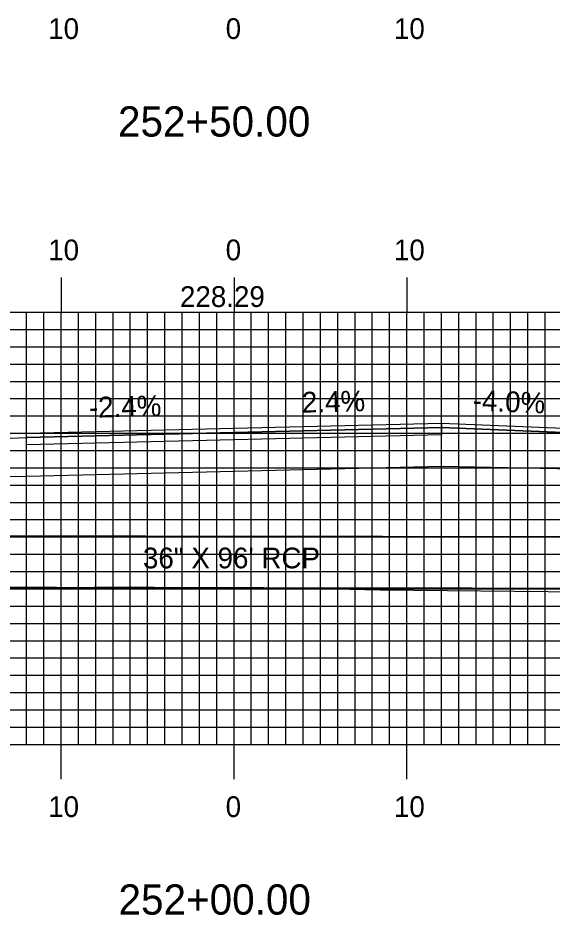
# Model space of a CAD drawing. Extents: x 1804290 to 1804634, y 442591 to 442811.
# Drawn here: x 1804443.7 to 1804474.6, y 442643.8 to 442695.7 of the extents above; entities that cross this region are included whole.
import ezdxf

# ---------------------------------------------------------------- set-up
doc = ezdxf.new("R2010")
doc.units = 0
for name, color, linetype in [('ANNOTATION', 7, 'Continuous'), ('D_Drainage_Culvert', 7, 'Continuous'), ('D_Drainage_Text', 7, 'Continuous'), ('D_Roadway_Centerline', 7, 'Continuous'), ('D_Roadway_Centerline_Text', 7, 'Continuous'), ('D_Roadway_Edge_Shoulder', 7, 'Continuous'), ('D_Roadway_Edge_TW', 7, 'Continuous'), ('D_Roadway_Pavement', 7, 'Continuous'), ('D_Roadway_SubGrade', 7, 'Continuous'), ('H_V ANNOTATION', 7, 'Continuous'), ('MAJOR', 7, 'Continuous'), ('MINOR', 7, 'Continuous'), ('S_Roadway_Centerline', 7, 'Continuous')]:
    doc.layers.add(name, color=color, linetype=linetype)

msp = doc.modelspace()

# ---------------------------------------------------------------- linework, layer by layer
at = {"layer": 'D_Drainage_Culvert'}
for p, q in [((1804453.167, 442663.676), (1804460.167, 442663.666)), ((1804407.504, 442662.794), (1804505.89, 442662.656))]:
    msp.add_line(p, q, dxfattribs=at)
msp.add_lwpolyline([(1804409.888, 442662.791), (1804409.893, 442665.791), (1804505.893, 442665.645), (1804505.888, 442662.645)], close=True, dxfattribs=at)
at = {"layer": 'D_Roadway_Edge_Shoulder'}
for points in [[(1804468.167, 442672.244), (1804476.167, 442671.924), (1804476.167, 442671.674), (1804468.167, 442671.994)], [(1804444.167, 442671.668), (1804436.167, 442671.348), (1804436.167, 442671.098), (1804444.167, 442671.418)]]:
    msp.add_lwpolyline(points, close=True, dxfattribs=at)
at = {"layer": 'D_Roadway_Edge_TW'}
msp.add_lwpolyline([(1804444.167, 442671.418), (1804444.167, 442671.668), (1804456.167, 442671.956), (1804468.167, 442672.244), (1804468.167, 442671.994), (1804456.167, 442671.706)], close=True, dxfattribs=at)
at = {"layer": 'D_Roadway_Pavement'}
msp.add_lwpolyline([(1804444.167, 442671.002), (1804444.167, 442671.418), (1804456.167, 442671.706), (1804468.167, 442671.994), (1804468.167, 442671.578), (1804456.167, 442671.29)], close=True, dxfattribs=at)
at = {"layer": 'D_Roadway_SubGrade'}
msp.add_lwpolyline([(1804444.167, 442669.168), (1804425.993, 442668.805), (1804436.167, 442671.348), (1804436.167, 442671.098), (1804444.167, 442671.418), (1804456.167, 442671.706), (1804468.167, 442671.994), (1804476.167, 442671.674), (1804476.167, 442671.924), (1804486.341, 442669.381), (1804468.167, 442669.744), (1804456.167, 442669.456)], close=True, dxfattribs=at)
at = {"layer": 'MAJOR'}
for p, q in [((1804446.167, 442680.669), (1804446.167, 442678.665)), ((1804456.167, 442680.669), (1804456.167, 442678.665)), ((1804466.167, 442680.669), (1804466.167, 442678.665)), ((1804316.167, 442678.665), (1804596.167, 442678.665)), ((1804316.167, 442678.665), (1804596.167, 442678.665)), ((1804446.167, 442653.665), (1804446.167, 442678.665)), ((1804456.167, 442653.665), (1804456.167, 442678.665)), ((1804466.167, 442653.665), (1804466.167, 442678.665)), ((1804316.167, 442673.665), (1804596.167, 442673.665)), ((1804316.167, 442668.665), (1804596.167, 442668.665)), ((1804316.167, 442663.665), (1804596.167, 442663.665)), ((1804316.167, 442658.665), (1804596.167, 442658.665)), ((1804316.167, 442653.665), (1804596.167, 442653.665)), ((1804316.167, 442653.665), (1804596.167, 442653.665)), ((1804446.167, 442651.661), (1804446.167, 442653.665)), ((1804456.167, 442651.661), (1804456.167, 442653.665)), ((1804466.167, 442651.661), (1804466.167, 442653.665))]:
    msp.add_line(p, q, dxfattribs=at)
at = {"layer": 'MINOR'}
for p, q in [((1804444.167, 442653.665), (1804444.167, 442678.665)), ((1804445.167, 442653.665), (1804445.167, 442678.665)), ((1804447.167, 442653.665), (1804447.167, 442678.665)), ((1804448.167, 442653.665), (1804448.167, 442678.665)), ((1804449.167, 442653.665), (1804449.167, 442678.665)), ((1804450.167, 442653.665), (1804450.167, 442678.665)), ((1804451.167, 442653.665), (1804451.167, 442678.665)), ((1804452.167, 442653.665), (1804452.167, 442678.665)), ((1804453.167, 442653.665), (1804453.167, 442678.665)), ((1804454.167, 442653.665), (1804454.167, 442678.665)), ((1804455.167, 442653.665), (1804455.167, 442678.665)), ((1804457.167, 442653.665), (1804457.167, 442678.665)), ((1804458.167, 442653.665), (1804458.167, 442678.665)), ((1804459.167, 442653.665), (1804459.167, 442678.665)), ((1804460.167, 442653.665), (1804460.167, 442678.665)), ((1804461.167, 442653.665), (1804461.167, 442678.665)), ((1804462.167, 442653.665), (1804462.167, 442678.665)), ((1804463.167, 442653.665), (1804463.167, 442678.665)), ((1804464.167, 442653.665), (1804464.167, 442678.665)), ((1804465.167, 442653.665), (1804465.167, 442678.665)), ((1804467.167, 442653.665), (1804467.167, 442678.665)), ((1804468.167, 442653.665), (1804468.167, 442678.665)), ((1804469.167, 442653.665), (1804469.167, 442678.665)), ((1804470.167, 442653.665), (1804470.167, 442678.665)), ((1804471.167, 442653.665), (1804471.167, 442678.665)), ((1804472.167, 442653.665), (1804472.167, 442678.665)), ((1804473.167, 442653.665), (1804473.167, 442678.665)), ((1804474.167, 442653.665), (1804474.167, 442678.665)), ((1804316.167, 442677.665), (1804596.167, 442677.665)), ((1804316.167, 442676.665), (1804596.167, 442676.665)), ((1804316.167, 442675.665), (1804596.167, 442675.665)), ((1804316.167, 442674.665), (1804596.167, 442674.665)), ((1804316.167, 442672.665), (1804596.167, 442672.665)), ((1804316.167, 442671.665), (1804596.167, 442671.665)), ((1804316.167, 442670.665), (1804596.167, 442670.665)), ((1804316.167, 442669.665), (1804596.167, 442669.665)), ((1804316.167, 442667.665), (1804596.167, 442667.665)), ((1804316.167, 442666.665), (1804596.167, 442666.665)), ((1804316.167, 442665.665), (1804596.167, 442665.665)), ((1804316.167, 442664.665), (1804596.167, 442664.665)), ((1804316.167, 442662.665), (1804596.167, 442662.665)), ((1804316.167, 442661.665), (1804596.167, 442661.665)), ((1804316.167, 442660.665), (1804596.167, 442660.665)), ((1804316.167, 442659.665), (1804596.167, 442659.665)), ((1804316.167, 442657.665), (1804596.167, 442657.665)), ((1804316.167, 442656.665), (1804596.167, 442656.665)), ((1804316.167, 442655.665), (1804596.167, 442655.665)), ((1804316.167, 442654.665), (1804596.167, 442654.665))]:
    msp.add_line(p, q, dxfattribs=at)
at = {"layer": 'S_Roadway_Centerline'}
msp.add_lwpolyline([(1804392.455, 442662.786), (1804403.753, 442662.746), (1804414.339, 442662.882), (1804416.075, 442662.891), (1804434.951, 442662.77), (1804441.486, 442662.699), (1804450.248, 442662.785), (1804459.333, 442662.638), (1804461.991, 442662.67), (1804464.615, 442662.608), (1804482.103, 442662.436), (1804485.564, 442662.421), (1804488.839, 442662.416), (1804494.685, 442662.541), (1804511.409, 442662.696), (1804519.927, 442662.797)], dxfattribs=at)

# ---------------------------------------------------------------- texts
at = {"layer": 'ANNOTATION'}
for s, rotation, p in [('-2.4%', 1.3748, (1804447.787, 442672.556)), ('2.4%', 1.3748, (1804460.108, 442672.851)), ('-4.0%', 357.7094, (1804469.959, 442672.974))]:
    msp.add_text(s, height=1.2, rotation=rotation, dxfattribs=at).set_placement(p)
at = {"layer": 'D_Drainage_Text'}
msp.add_text('36" X 96\' RCP', height=1.2, dxfattribs=at).set_placement((1804450.899, 442663.849))
at = {"layer": 'D_Roadway_Centerline'}
for s, p in [('C', (1804456.162, 442671.956)), ('L', (1804456.167, 442671.949))]:
    msp.add_text(s, height=0.0146, dxfattribs=at).set_placement(p)
at = {"layer": 'D_Roadway_Centerline_Text'}
msp.add_text('228.29', height=1.2, dxfattribs=at).set_placement((1804453.042, 442678.967))
at = {"layer": 'H_V ANNOTATION'}
for s, height, p in [('10', 1.2, (1804445.418, 442694.465)), ('0', 1.2, (1804455.685, 442694.465)), ('10', 1.2, (1804465.418, 442694.465)), ('252+50.00', 1.75, (1804449.456, 442688.821)), ('10', 1.2, (1804445.418, 442681.665)), ('0', 1.2, (1804455.685, 442681.665)), ('10', 1.2, (1804465.418, 442681.665)), ('10', 1.2, (1804445.418, 442649.465)), ('0', 1.2, (1804455.685, 442649.465)), ('10', 1.2, (1804465.418, 442649.465)), ('252+00.00', 1.75, (1804449.487, 442643.821))]:
    msp.add_text(s, height=height, dxfattribs=at).set_placement(p)

doc.saveas('drawing.dxf')
